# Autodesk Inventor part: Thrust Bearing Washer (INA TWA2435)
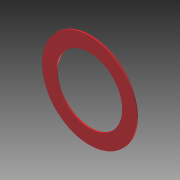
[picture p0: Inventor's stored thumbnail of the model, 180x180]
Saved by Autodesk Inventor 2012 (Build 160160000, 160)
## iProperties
Created: 2010-12
Part Number: Thrust Bearing Washer (INA TWA2435)
Document SubType Name: Modeling
Designer: Alex
Density: 7.85 g/cm^3
Material: Steel
Mass: 7.81707 g
Surface Area: 26.8827 cm^2
Volume: 0.995805 cm^3
Author: Alex Nagy
Title: Thrust Bearig Washer
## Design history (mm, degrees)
sketch "Sketch1"
  geometry: C1 r 27.483 at (0, 0); 2 further points
  constraints: 1 centre point
  dimensions: "d0" = 54.9656 diameter of C1
extrude "Extrusion1" new body sketch "Sketch1" distance "d1" = 0.8128; taper "d2" = 0 deg
hole "Hole1" diameter "d5" = 38.227; stored, may be unused: countersink angle "d9" = 82 deg, drill point angle "d11" = 118 deg; dims "d3" = 25.4, "d4" = 25.4, "d6" = 19.05, "d7" = 9.525, "d8" = 6.35, "d10" = 25.4
body "Solid1"
